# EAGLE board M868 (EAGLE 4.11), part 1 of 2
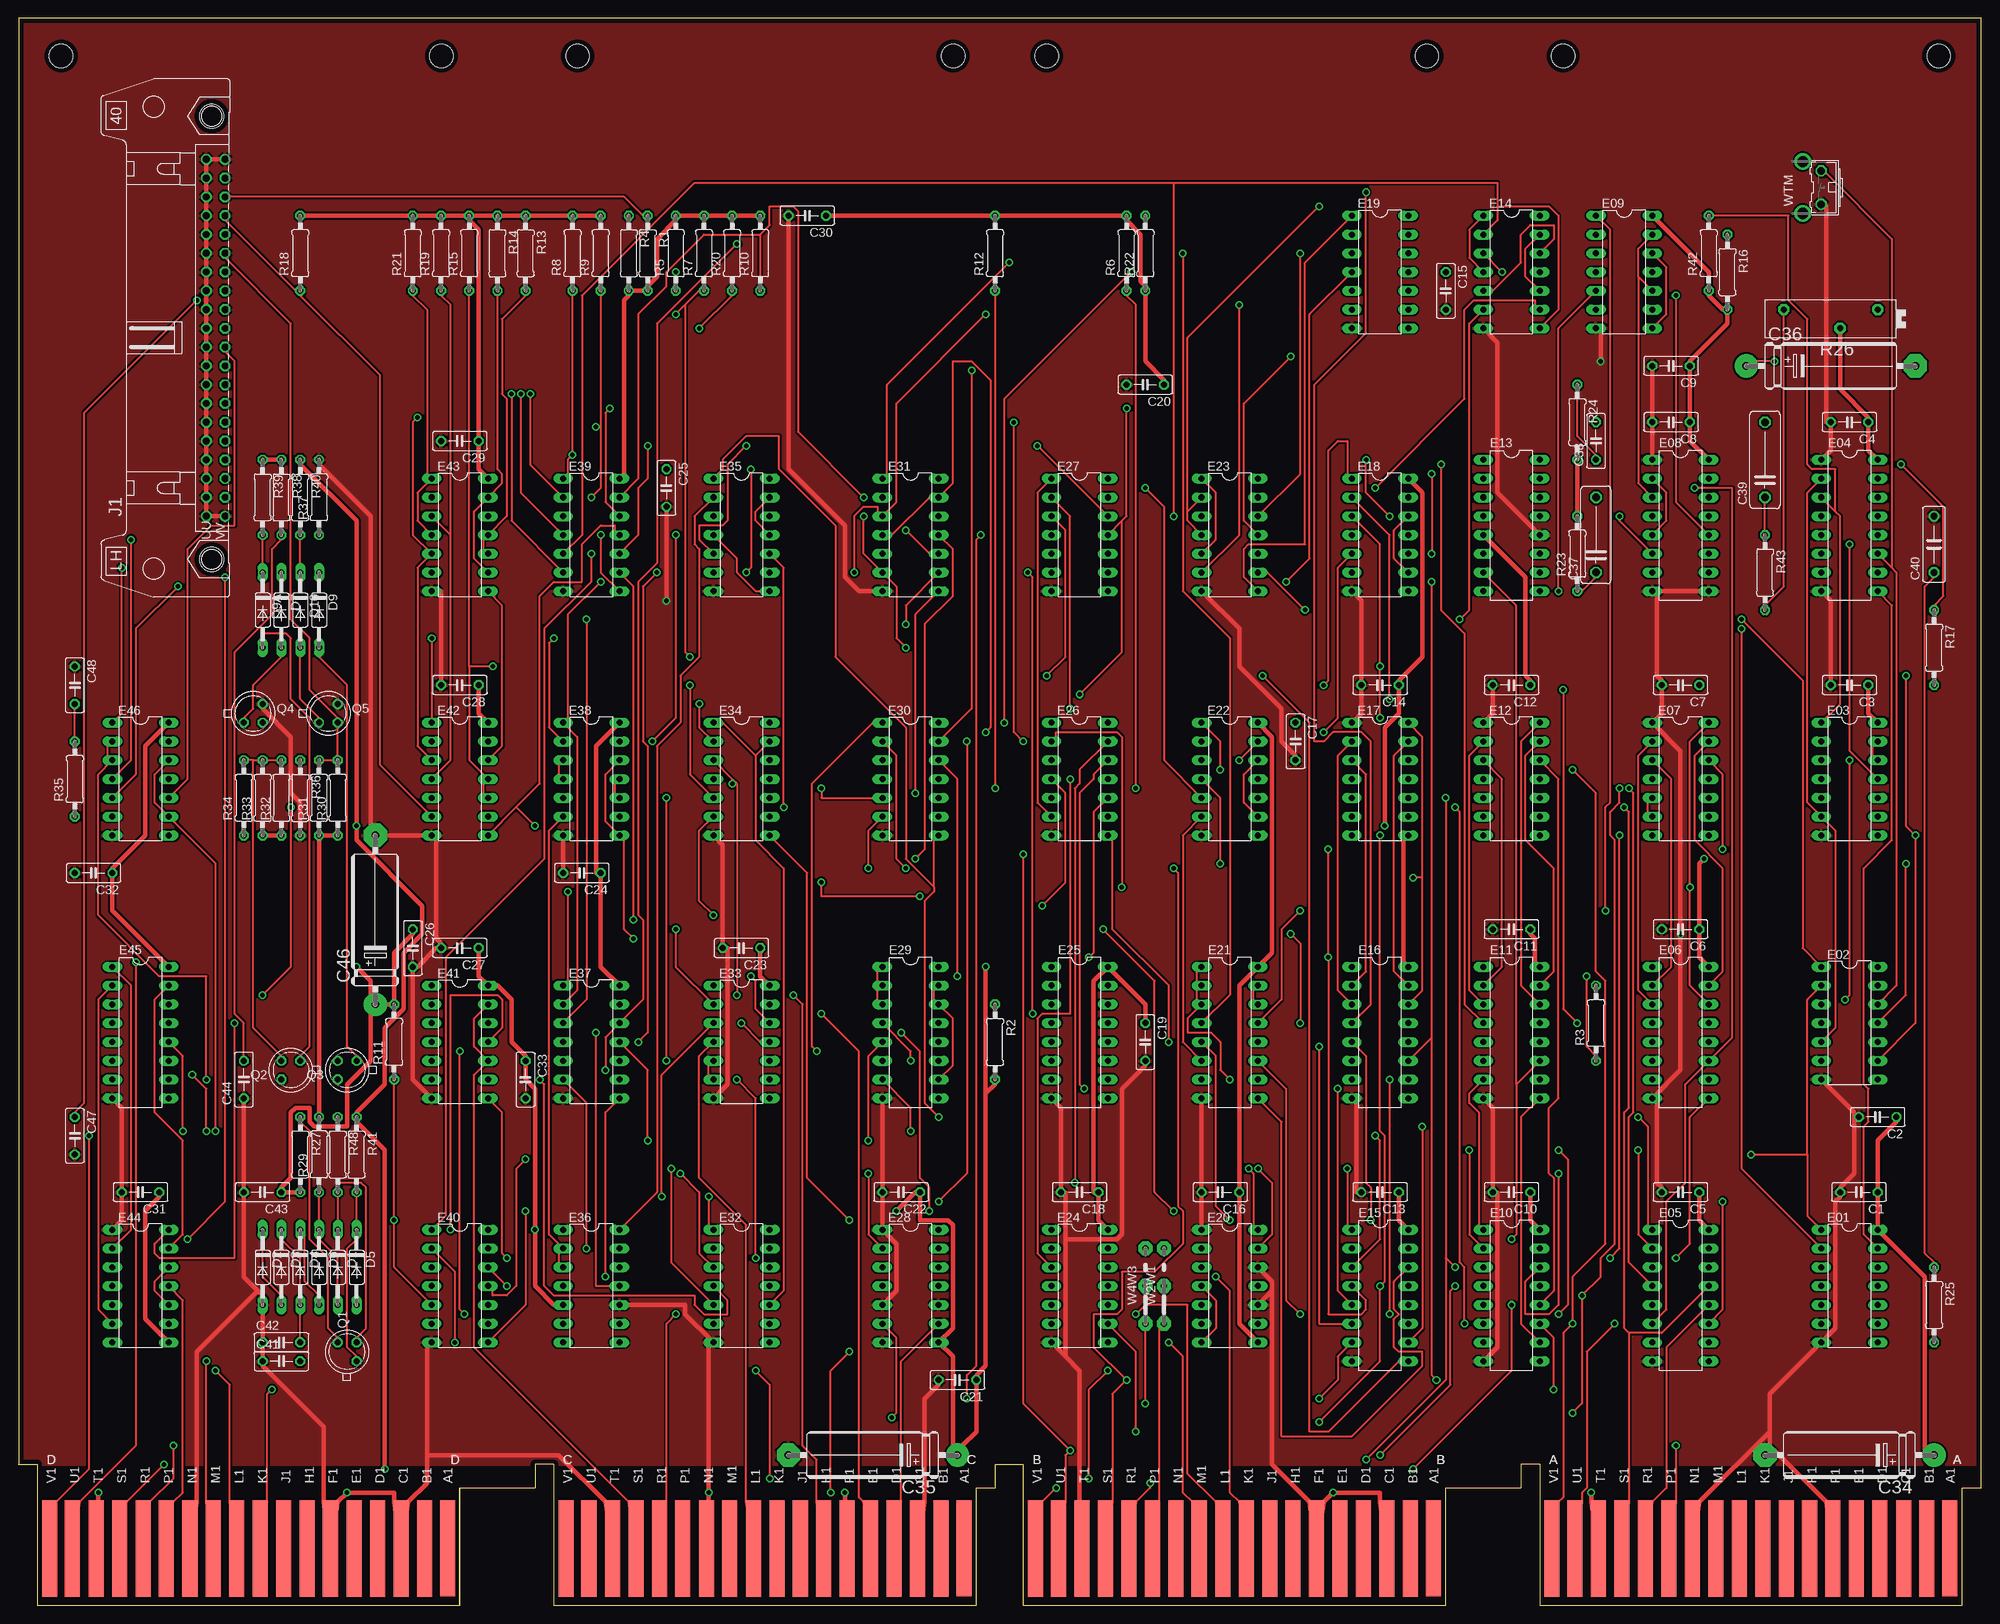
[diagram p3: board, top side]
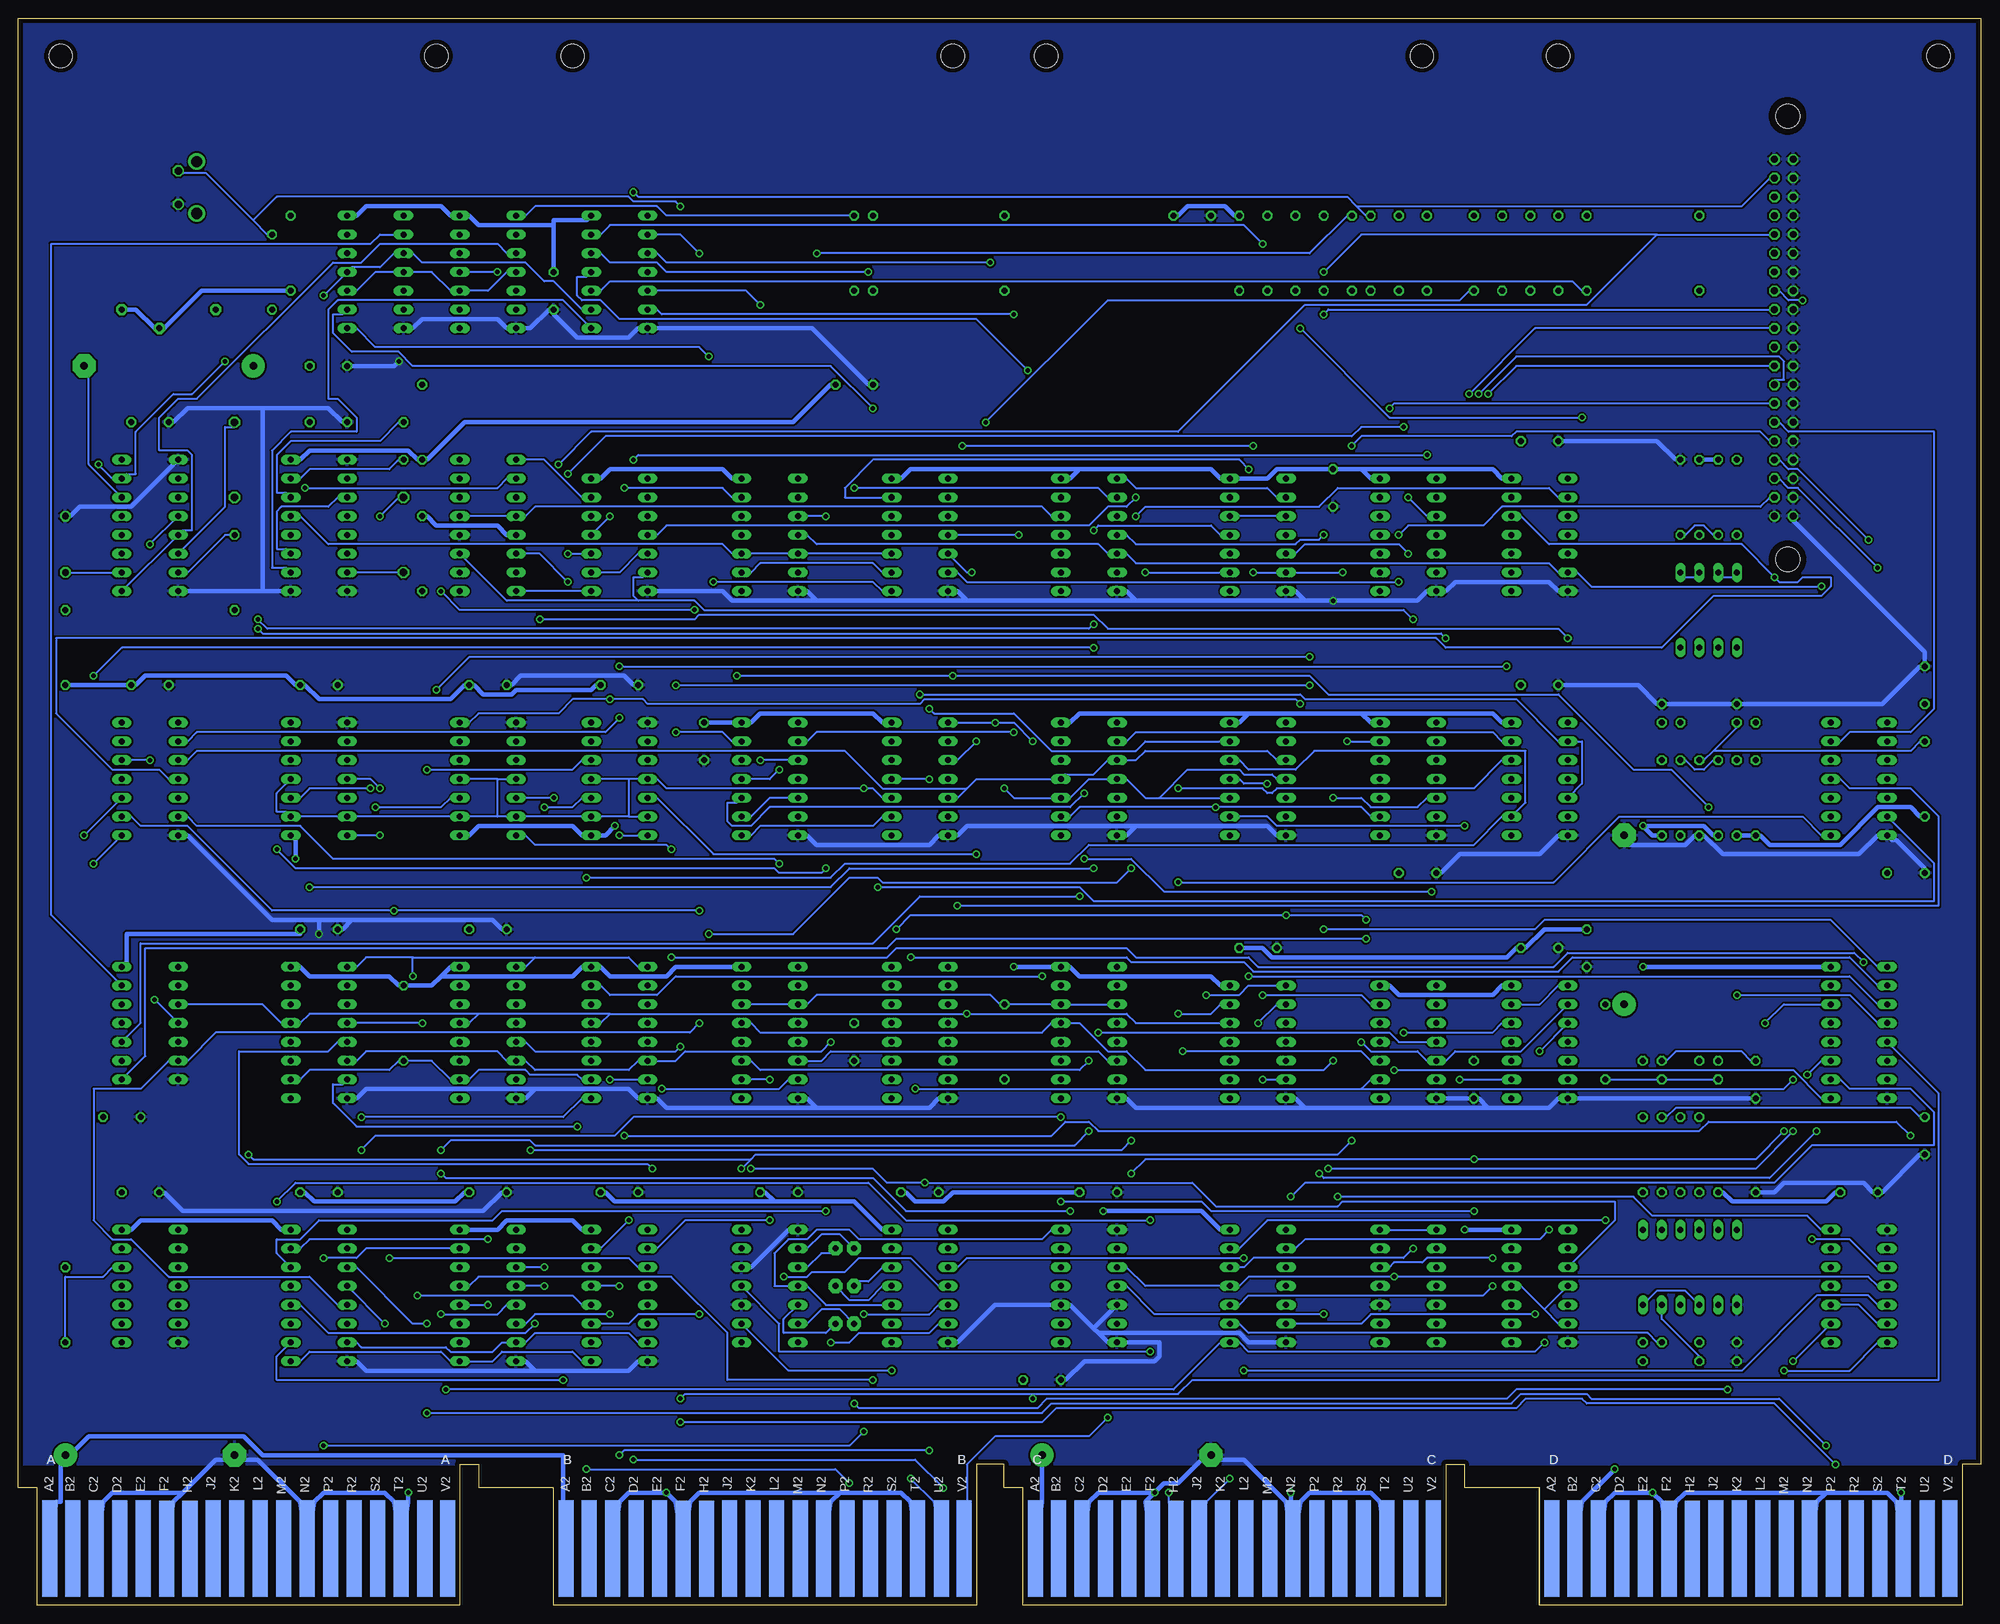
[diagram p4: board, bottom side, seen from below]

Size 265.43 x 214.63 mm. Coordinates in mm from the lower left corner, seen from the top.
Copper layers (1*16): Top 0.035mm / dielectric 1.5mm / Bottom 0.035mm
Design rules "10mils": minimum track width 10mil, minimum drill 24mil, track to track 10mil, track to pad 10mil, pad to pad 10mil, via to via 10mil, smd to smd 10mil, copper to edge 25mil, drill to drill 10mil, minimum pad ring 10mil, minimum via ring 8mil, stop-mask expansion 0mil, vias tented up to drill 0mil, thermal gap 10mil
Net classes: 1 supply: width 0.635 mm

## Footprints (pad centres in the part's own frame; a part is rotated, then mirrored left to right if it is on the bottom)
C050-025X075 = drill 0.813 octagon: 1 -2.54,0; 2 2.54,0
E22-6 = drill 1.016 pad 3.15 round: + -11.43,0 | drill 1.016 pad 3.15 octagon: - 11.43,0
C102-043X133 = drill 1.016 octagon: 1 -5.08,0; 2 5.08,0
C075-032X103 = drill 0.914 octagon: 1 -3.81,0; 2 3.81,0
DO35-10 = drill 0.813 long: A 5.08,0; C -5.08,0
DIL14 = drill 0.813 long: 1 -7.62,-3.81; 2 -5.08,-3.81; 3 -2.54,-3.81; 4 0,-3.81; 5 2.54,-3.81; 6 5.08,-3.81; 7 7.62,-3.81; 8 7.62,3.81; 9 5.08,3.81; 10 2.54,3.81; 11 0,3.81; 12 -2.54,3.81; 13 -5.08,3.81; 14 -7.62,3.81
DIL16 = drill 0.813 long: 1 -8.89,-3.81; 2 -6.35,-3.81; 3 -3.81,-3.81; 4 -1.27,-3.81; 5 1.27,-3.81; 6 3.81,-3.81; 7 6.35,-3.81; 8 8.89,-3.81; 9 8.89,3.81; 10 6.35,3.81; 11 3.81,3.81; 12 1.27,3.81; 13 -1.27,3.81; 14 -3.81,3.81; 15 -6.35,3.81; 16 -8.89,3.81
EDGE-CON8 = smd 2.032 x 13.017: AA1 261.223,7.709; AB1 258.118,7.684; AC1 254.956,7.684; AD1 251.765,7.684; AE1 248.59,7.693; AF1 245.389,7.668; AH1 242.24,7.668; AJ1 239.09,7.668; AK1 235.915,7.668; AL1 232.74,7.693; AM1 229.54,7.693; AN1 226.39,7.693; AP1 223.19,7.668; AR1 220.04,7.668; AS1 216.865,7.693; AT1 213.69,7.693; AU1 210.49,7.693; AV1 207.404,7.668; BA1 191.373,7.709; BB1 188.268,7.684; BC1 185.106,7.684; BD1 181.915,7.684; BE1 178.74,7.693; BF1 175.539,7.668; BH1 172.39,7.668; BJ1 169.24,7.668; BK1 166.065,7.668; BL1 162.89,7.693; BM1 159.69,7.693; BN1 156.54,7.693; BP1 153.34,7.668; BR1 150.19,7.668; BS1 147.015,7.693; BT1 143.84,7.693; BU1 140.64,7.693; BV1 137.554,7.668; CA1 127.873,7.709; CB1 124.768,7.684; CC1 121.606,7.684; CD1 118.415,7.684; CE1 115.24,7.693; CF1 112.039,7.668; CH1 108.89,7.668; CJ1 105.74,7.668; CK1 102.565,7.668; CL1 99.39,7.693; CM1 96.19,7.693; CN1 93.04,7.693; CP1 89.84,7.668; CR1 86.69,7.668; CS1 83.515,7.693; CT1 80.34,7.693; CU1 77.14,7.693; CV1 74.054,7.668; DA1 58.023,7.709; DB1 54.918,7.684; DC1 51.756,7.684; DD1 48.565,7.684; DE1 45.39,7.693; DF1 42.189,7.668; DH1 39.04,7.668; DJ1 35.89,7.668; DK1 32.715,7.668; DL1 29.54,7.693; DM1 26.34,7.693; DN1 23.19,7.693; DP1 19.99,7.668; DR1 16.84,7.668; DS1 13.665,7.693; DT1 10.49,7.693; DU1 7.29,7.693; DV1 4.204,7.668 | smd 2.032 x 13.017 bottom: AA2 261.223,7.69; AB2 258.102,7.668; AC2 254.94,7.668; AD2 251.765,7.693; AE2 248.59,7.693; AF2 245.389,7.642; AH2 242.24,7.642; AJ2 239.09,7.668; AK2 235.915,7.668; AL2 232.74,7.693; AM2 229.54,7.693; AN2 226.39,7.693; AP2 223.19,7.668; AR2 220.04,7.668; AS2 216.865,7.693; AT2 213.69,7.693; AU2 210.464,7.693; AV2 207.404,7.668; BA2 191.373,7.69; BB2 188.252,7.668; BC2 185.09,7.668; BD2 181.915,7.693; BE2 178.74,7.693; BF2 175.539,7.642; BH2 172.39,7.642; BJ2 169.24,7.668; BK2 166.065,7.668; BL2 162.89,7.693; BM2 159.69,7.693; BN2 156.54,7.693; BP2 153.34,7.668; BR2 150.19,7.668; BS2 147.015,7.693; BT2 143.84,7.693; BU2 140.614,7.693; BV2 137.554,7.668; CA2 127.873,7.69; CB2 124.752,7.668; CC2 121.59,7.668; CD2 118.415,7.693; CE2 115.24,7.693; CF2 112.039,7.642; CH2 108.89,7.642; CJ2 105.74,7.668; CK2 102.565,7.668; CL2 99.39,7.693; CM2 96.19,7.693; CN2 93.04,7.693; CP2 89.84,7.668; CR2 86.69,7.668; CS2 83.515,7.693; CT2 80.34,7.693; CU2 77.114,7.693; CV2 74.054,7.668; DA2 58.023,7.69; DB2 54.902,7.668; DC2 51.74,7.668; DD2 48.565,7.693; DE2 45.39,7.693; DF2 42.189,7.642; DH2 39.04,7.642; DJ2 35.89,7.668; DK2 32.715,7.668; DL2 29.54,7.693; DM2 26.34,7.693; DN2 23.19,7.693; DP2 19.99,7.668; DR2 16.84,7.668; DS2 13.665,7.693; DT2 10.49,7.693; DU2 7.264,7.693; DV2 4.204,7.668
DEC40PINH = drill 0.914 octagon: A 24.13,1.27; AA -3.81,1.27; B 24.13,-1.27; BB -3.81,-1.27; C 21.59,1.27; CC -6.35,1.27; D 21.59,-1.27; DD -6.35,-1.27; E 19.05,1.27; EE -8.89,1.27; F 19.05,-1.27; FF -8.89,-1.27; H 16.51,1.27; HH -11.43,1.27; J 16.51,-1.27; JJ -11.43,-1.27; K 13.97,1.27; KK -13.97,1.27; L 13.97,-1.27; LL -13.97,-1.27; M 11.43,1.27; MM -16.51,1.27; N 11.43,-1.27; NN -16.51,-1.27; P 8.89,1.27; PP -19.05,1.27; R 8.89,-1.27; RR -19.05,-1.27; S 6.35,1.27; SS -21.59,1.27; T 6.35,-1.27; TT -21.59,-1.27; U 3.81,1.27; UU -24.13,1.27; V 3.81,-1.27; W 1.27,1.27; X 1.27,-1.27; Y -1.27,1.27; Z -1.27,-1.27 | drill 0.914 round: VV -24.13,-1.27 | hole 3.302: -29.972,0.533; 29.972,0.533
TO18 = drill 0.813 octagon: 1 -1.27,-1.27; 2 1.27,-1.27; 3 1.27,1.27
0207/10 = drill 0.813 octagon: 1 -5.08,0; 2 5.08,0
PT-SPIN = drill 0.813 pad 1.524 octagon: 1 -6.35,-1.27; 2 6.35,-1.27; 3 -1.27,1.27
OMNIBUS = hole 3.175: 208.915,209.55; 259.715,209.55; 190.5,209.55; 139.065,209.55; 75.616,209.55; 126.416,209.55; 57.201,209.55; 5.766,209.55
05C = drill 0.813 pad 1.905 octagon: 1 -2.54,0; 2 2.54,0; 3 7.62,0
B3F-31XX = drill 1.016 octagon: 1 -2.261,-1.245; 2 2.261,-1.245 | drill 1.499 pad 2.159 round: 3 -3.505,1.245; 4 3.505,1.245

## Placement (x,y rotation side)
C1  .01  [C050-025X075]  248.92,55.88 180 top
C2  .01  [C050-025X075]  251.46,66.04 180 top
C3  .01  [C050-025X075]  247.65,124.46 180 top
C4  .01  [C050-025X075]  247.65,160.02 180 top
C5  .01  [C050-025X075]  224.79,55.88 180 top
C6  .01  [C050-025X075]  224.79,91.44 180 top
C7  .01  [C050-025X075]  224.79,124.46 180 top
C8  .01  [C050-025X075]  223.52,160.02 180 top
C9  .01  [C050-025X075]  223.52,167.64 180 top
C10  .01  [C050-025X075]  201.93,55.88 180 top
C11  .01  [C050-025X075]  201.93,91.44 180 top
C12  .01  [C050-025X075]  201.93,124.46 180 top
C13  .01  [C050-025X075]  184.15,55.88 180 top
C14  .01  [C050-025X075]  184.15,124.46 180 top
C15  .01  [C050-025X075]  193.04,177.8 270 top
C16  .01  [C050-025X075]  162.56,55.88 180 top
C17  .01  [C050-025X075]  172.72,116.84 270 top
C18  .01  [C050-025X075]  143.51,55.88 180 top
C19  .01  [C050-025X075]  152.4,76.2 270 top
C20  .01  [C050-025X075]  152.4,165.1 180 top
C21  .01  [C050-025X075]  127,30.48 180 top
C22  .01  [C050-025X075]  119.38,55.88 180 top
C23  .01  [C050-025X075]  97.79,88.9 180 top
C24  .01  [C050-025X075]  76.2,99.06 180 top
C25  .01  [C050-025X075]  87.63,151.13 270 top
C26  .01  [C050-025X075]  53.34,88.9 270 top
C27  .01  [C050-025X075]  59.69,88.9 180 top
C28  .01  [C050-025X075]  59.69,124.46 180 top
C29  .01  [C050-025X075]  59.69,157.48 180 top
C30  .01  [C050-025X075]  106.68,187.96 180 top
C31  .01  [C050-025X075]  16.51,55.88 180 top
C32  .01  [C050-025X075]  10.16,99.06 180 top
C33  .01  [C050-025X075]  68.58,71.12 270 top
C34  6.8  [E22-6]  247.65,20.32 180 top
C35  6.8  [E22-6]  115.57,20.32 180 top
C36  6.8  [E22-6]  245.11,167.64 0 top
C37  2700pf  [C102-043X133]  213.36,144.78 90 top
C38  27pf  [C050-025X075]  213.36,157.48 90 top
C39  2700pf  [C102-043X133]  236.22,154.94 90 top
C40  560pf  [C075-032X103]  259.08,143.51 90 top
C41  .01  [C050-025X075]  35.56,33.02 0 top
C42  .01  [C050-025X075]  35.56,35.56 0 top
C43  .01  [C050-025X075]  33.02,55.88 180 top
C44  .01  [C050-025X075]  30.48,71.12 90 top
C46  6.8  [E22-6]  48.26,92.71 90 top
C47  .01  [C050-025X075]  7.62,63.5 270 top
C48  .01  [C050-025X075]  7.62,124.46 270 top
D1  D664  [DO35-10]  43.18,45.72 270 top
D2  D662  [DO35-10]  33.02,45.72 270 top
D3  D662  [DO35-10]  35.56,45.72 270 top
D4  D662  [DO35-10]  38.1,45.72 270 top
D5  D664  [DO35-10]  45.72,45.72 270 top
D6  D662  [DO35-10]  40.64,45.72 270 top
D7  D664  [DO35-10]  35.56,134.62 270 top
D9  D664  [DO35-10]  40.64,134.62 270 top
D9A  D664  [DO35-10]  33.02,134.62 270 top
D10  D664  [DO35-10]  38.1,134.62 270 top
E01  74H04N  [DIL14]  247.65,43.18 270 top
E02  7402N  [DIL14]  247.65,78.74 270 top
E03  7474N  [DIL14]  247.65,111.76 270 top
E04  74123N  [DIL16]  247.65,146.05 270 top
E05  DEC8235  [DIL16]  224.79,41.91 270 top
E06  DEC8271  [DIL16]  224.79,77.47 270 top
E07  SP380N  [DIL14]  224.79,111.76 270 top
E08  74123N  [DIL16]  224.79,146.05 270 top
E09  7474N  [DIL14]  217.17,180.34 270 top
E10  DEC8235  [DIL16]  201.93,41.91 270 top
E11  DEC8271  [DIL16]  201.93,77.47 270 top
E12  SP380N  [DIL14]  201.93,111.76 270 top
E13  7475N  [DIL16]  201.93,146.05 270 top
E14  7474N  [DIL14]  201.93,180.34 270 top
E15  DEC8235  [DIL16]  184.15,41.91 270 top
E16  DEC8271  [DIL16]  184.15,77.47 270 top
E17  SP380N  [DIL14]  184.15,111.76 270 top
E18  DEC8242  [DIL14]  184.15,144.78 270 top
E19  7400N  [DIL14]  184.15,180.34 270 top
E20  SP380N  [DIL14]  163.83,43.18 270 top
E21  DEC8271  [DIL16]  163.83,77.47 270 top
E22  7400N  [DIL14]  163.83,111.76 270 top
E23  7410N  [DIL14]  163.83,144.78 270 top
E24  SP314N  [DIL14]  143.51,43.18 270 top
E25  [DIL16]  143.51,77.47 270 top
E26  7404N  [DIL14]  143.51,111.76 270 top
E27  7410N  [DIL14]  143.51,144.78 270 top
E28  SP384N  [DIL14]  120.65,43.18 270 top
E29  DEC8271  [DIL16]  120.65,77.47 270 top
E30  7474N  [DIL14]  120.65,111.76 270 top
E31  7404N  [DIL14]  120.65,144.78 270 top
E32  7404N  [DIL14]  97.79,43.18 270 top
E33  DS8881N  [DIL14]  97.79,76.2 270 top
E34  7474N  [DIL14]  97.79,111.76 270 top
E35  7410N  [DIL14]  97.79,144.78 270 top
E36  74LS93N  [DIL14]  77.47,43.18 270 top
E37  7402N  [DIL14]  77.47,76.2 270 top
E38  7400N  [DIL14]  77.47,111.76 270 top
E39  7417N  [DIL14]  77.47,144.78 270 top
E40  7430N  [DIL14]  59.69,43.18 270 top
E41  DS8881N  [DIL14]  59.69,76.2 270 top
E42  DEC8242  [DIL14]  59.69,111.76 270 top
E43  7401N  [DIL14]  59.69,144.78 270 top
E44  SP380N  [DIL14]  16.51,43.18 270 top
E45  DEC8251  [DIL16]  16.51,77.47 270 top
E46  7401N  [DIL14]  16.51,111.76 270 top
EDGE$  [EDGE-CON8]  0,0 0 top
J1  [DEC40PINH]  26.67,171.45 90 top
Q1  MPS6534  [TO18]  44.45,34.29 90 top
Q2  MPS6534  [TO18]  36.83,72.39 180 top
Q3  MPS6534  [TO18]  44.45,72.39 180 top
Q4  MPS6534  [TO18]  31.75,120.65 0 top
Q5  MPS6534  [TO18]  41.91,120.65 0 top
R1  270  [0207/10]  85.09,182.88 270 top
R2  1K  [0207/10]  132.08,76.2 270 top
R3  1K  [0207/10]  213.36,78.74 90 top
R4  270  [0207/10]  82.55,182.88 270 top
R5  270  [0207/10]  88.9,182.88 90 top
R6  560  [0207/10]  149.86,182.88 90 top
R7  270  [0207/10]  92.71,182.88 90 top
R8  470  [0207/10]  74.93,182.88 90 top
R9  470  [0207/10]  78.74,182.88 90 top
R10  470  [0207/10]  100.33,182.88 90 top
R11  6.8K  [0207/10]  50.8,76.2 90 top
R12  1K  [0207/10]  132.08,182.88 90 top
R13  470  [0207/10]  68.58,182.88 270 top
R14  470  [0207/10]  64.77,182.88 270 top
R15  470  [0207/10]  60.96,182.88 90 top
R16  1.5K  [0207/10]  231.14,180.34 270 top
R17  51K  [0207/10]  259.08,129.54 270 top
R18  270  [0207/10]  38.1,182.88 90 top
R19  470  [0207/10]  57.15,182.88 90 top
R20  470  [0207/10]  96.52,182.88 90 top
R21  470  [0207/10]  53.34,182.88 90 top
R22  1K  [0207/10]  152.4,182.88 90 top
R23  10K  [0207/10]  210.82,142.24 90 top
R24  4.7K  [0207/10]  210.82,160.02 270 top
R25  220  [0207/10]  259.08,40.64 270 top
R26  10K  [PT-SPIN]  245.11,173.99 180 top
R27  1.5K  [0207/10]  38.1,60.96 270 top
R29  1.5K  [0207/10]  40.64,60.96 90 top
R30  1K  [0207/10]  43.18,109.22 90 top
R31  1K  [0207/10]  40.64,109.22 90 top
R32  1K  [0207/10]  35.56,109.22 90 top
R33  1K  [0207/10]  33.02,109.22 90 top
R34  1K  [0207/10]  30.48,109.22 90 top
R35  1.21K 1%  [0207/10]  7.62,111.76 90 top
R36  562 1%  [0207/10]  38.1,109.22 270 top
R37  1.5K  [0207/10]  40.64,149.86 90 top
R38  1K  [0207/10]  35.56,149.86 270 top
R39  1.5K  [0207/10]  33.02,149.86 270 top
R40  1K  [0207/10]  38.1,149.86 270 top
R41  3K  [0207/10]  45.72,60.96 270 top
R42  1K  [0207/10]  228.6,182.88 90 top
R43  4.7K  [0207/10]  236.22,139.7 270 top
R48  470  [0207/10]  43.18,60.96 270 top
U$1  OUTLINE-OMNIBUS  [OMNIBUS]  0,0 0 top
W2W1  [05C]  154.94,40.64 90 top
W4W3  [05C]  152.4,40.64 90 top
WTM  [B3F-31XX]  242.57,191.77 90 top

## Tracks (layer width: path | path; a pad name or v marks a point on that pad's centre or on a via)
-1.5V
  Top 0.254: C42.2 D4.A 38.1,46.99 35.56,49.53 D3.C
  Bottom 0.254: D5.A 43.81,42.55 40.01,42.55 D4.A
-3V
  Top 0.254: R29.1 D6.C 40.64,49.53 43.18,46.99 D1.A
  Bottom 0.254: C41.2 38.1,33.66 43.18,38.74 D1.A
-4.7V
  Top 0.254: R35.2 C48.2
  Bottom 0.254: 36.2,115.57 33.02,118.75 Q4.2 | 36.2,115.57 37.47,114.3 R36.1 | 36.2,115.57 9.53,115.57 8.26,116.84 R35.2
-9V
  Top 0.254: R38.2 35.56,144.15 34.29,142.88 34.29,133.99 29.21,128.91 29.21,80.01 30.48,78.74 C44.2
  Bottom 0.254: R38.2 36.2,144.78 37.47,146.05 38.73,146.05 40.01,144.78 R37.1 | C44.2 31.11,73.66 32.38,74.93 41.27,74.93 42.55,73.66 Q3.2
-15V  (via drill 0.61)
  Top 0.635: v49.53,18.42 49.53,61.6 45.72,65.41 R41.1 45.72,66.68 49.53,70.49 49.53,78.11 52.07,80.65 52.07,88.27 54.61,90.81 54.61,94.62 45.72,103.51 v45.72,105.41 45.72,146.69 38.1,154.31 R40.1 | R32.1 R33.1 | R38.1 R39.1 | R29.2 R31.1 R30.1
  Bottom 0.635: v49.53,18.42 53.98,13.97 EDGE$.DB2 | R33.1 R34.1 29.84,104.14 28.57,102.87 19.05,102.87 13.97,107.95 9.53,107.95 8.26,106.68 R35.1 | R40.1 R38.1 | R30.1 44.45,104.14 v45.72,105.41 37.47,105.41 36.2,104.14 R32.1
C0  (via drill 0.61)
  Top 0.254: v108.58,80.01 113.67,74.93 113.67,14.61 114.3,13.97 EDGE$.CE1
  Bottom 0.254: v108.58,80.01 104.14,80.01 102.87,81.28 E33.13
C1  (via drill 0.61)
  Top 0.254: v104.78,82.55 106.05,81.28 106.05,21.59 107.95,19.69 107.95,13.97 EDGE$.CH1
  Bottom 0.254: v104.78,82.55 100.33,82.55 99.06,83.82 E33.1
CC_67X  (via drill 0.61)
  Top 0.254: E33.6 93.34,71.76 93.34,73.03 E33.5 | v142.24,111.76 142.24,80.01 138.43,80.01 137.79,79.38 137.79,47.63 E24.3 | v97.16,71.12 99.69,68.58 v99.69,46.99
  Bottom 0.254: v142.24,111.76 E26.11 | v99.69,46.99 137.16,46.99 138.43,45.72 E24.3 | v97.16,71.12 E33.6
CC_67X\  (via drill 0.61)
  Top 0.254: E45.2 10.79,81.92 10.79,40.01 E44.6 | E44.12 18.41,43.82 18.41,42.55 E44.10 | E07.6 220.34,107.32 220.34,108.59 E07.5 | v151.13,110.49 151.13,175.9 149.86,177.17 R6.1 | v144.78,87.63 145.41,88.27 145.41,107.32 E26.10
  Bottom 0.254: E44.6 13.97,38.1 16.51,40.64 E44.10 | E07.11 230.5,109.86 230.5,107.32 229.24,107.32 E07.9 E07.6 E12.9 200.66,106.68 | 200.66,106.68 E12.6 E17.9 182.88,106.68 | 200.66,111.76 E12.4 | 200.66,111.76 E12.11 | 200.66,106.68 200.66,111.76 | 182.88,106.68 E17.6 | E26.10 148.59,109.22 149.86,110.49 v151.13,110.49 177.8,110.49 179.07,111.76 E17.4 182.88,111.76 | 182.88,111.76 E17.11 | 182.88,111.76 182.88,106.68 | v144.78,87.63 115.57,87.63 114.94,87 99.69,87 98.42,85.73 57.15,85.73 55.24,87.63 17.78,87.63 13.97,83.82 E45.2
CC_BTP3  (via drill 0.61)
  Top 0.254: v233.04,132.08 233.04,59.06 E01.2 | v72.39,130.81 71.75,130.18 71.75,118.75 E38.2
  Bottom 0.254: v233.04,132.08 232.41,131.45 73.03,131.45 v72.39,130.81
CC_CLK_TE\
  Top 0.254: E26.6 137.79,108.59 137.79,150.5 E27.1
CC_DTP
  Top 0.254: E23.1 161.93,150.5 161.93,144.15 E23.5
  Bottom 0.254: E27.10 E23.5 E23.10 168.91,142.24 170.18,143.51 223.52,143.51 227.33,147.32 E08.13
CC_DTP0  (via drill 0.61)
  Top 0.254: v113.03,139.7 113.03,147.32 114.3,148.59 116.2,148.59 116.2,147.96 E31.3 118.75,149.23 118.75,162.56 v130.81,174.63
  Bottom 0.254: v113.03,139.7 E35.9 | v130.81,174.63 178.44,174.63 179.07,175.26 E19.6
CC_DTP0\  (via drill 0.61)
  Top 0.254: v85.72,116.84 88.9,120.02 v88.9,144.78 | E31.4 118.11,144.78 123.19,149.86 E31.13 126.36,151.77 126.36,168.28 128.91,168.28 131.44,165.74 131.44,118.75 v130.81,118.11
  Bottom 0.254: v88.9,144.78 89.53,144.15 92.08,144.15 92.71,143.51 114.3,143.51 115.57,144.78 E31.4 | v85.72,116.84 E38.13 | v130.81,118.11 157.48,118.11 158.75,116.84 E22.2
CC_DTP1  (via drill 0.61)
  Top 0.254: v133.99,181.61 117.47,165.1 117.47,153.04 E31.1 | E36.14 86.36,55.88 86.36,116.21 89.53,119.38 89.53,125.73 92.08,128.27 92.08,142.88 91.44,143.51 91.44,147.32 E35.2
  Bottom 0.254: E36.14 E36.1 | E35.2 95.25,149.86 96.52,151.13 114.3,151.13 115.57,152.4 E31.1 | v133.99,181.61 177.8,181.61 179.07,182.88 E19.3
CC_DTP1\  (via drill 0.61)
  Top 0.254: v152.4,151.13 154.94,148.59 154.94,114.3 E22.5 | E22.12 165.74,112.4 165.74,108.59 E22.9
  Bottom 0.254: v152.4,151.13 119.38,151.13 118.11,149.86 E31.2 | E22.9 166.37,106.68 163.83,109.22 E22.5
CC_F/R  (via drill 0.61)
  Top 0.254: v90.81,124.46 90.81,112.4 E34.5 | v176.53,124.46 177.16,125.1 177.16,156.21 178.44,157.48 179.71,157.48 179.71,153.04 E18.1
  Bottom 0.254: v176.53,124.46 v90.81,124.46
CC_F/R\  (via drill 0.61)
  Top 0.254: v156.21,53.34 153.67,55.88 153.67,84.46 v146.69,91.44 | v93.98,93.35 92.08,95.25 92.08,104.78 E34.6 | v83.19,92.71 83.19,137.8 E39.9
  Bottom 0.254: v156.21,53.34 200.03,53.34 201.29,52.07 224.79,52.07 227.33,49.53 230.5,49.53 230.5,47.63 E05.14 | v146.69,91.44 144.78,93.35 v93.98,93.35 83.82,93.35 v83.19,92.71
CC_INIT  (via drill 0.61)
  Top 0.254: v79.38,44.45 79.38,66.68 E37.8
  Bottom 0.254: E44.4 13.97,43.18 15.24,44.45 v79.38,44.45 99.06,44.45 100.33,43.18 E32.11 113.03,43.18 115.57,45.72 E28.3
CC_INIT\  (via drill 0.61)
  Top 0.254: 99.69,114.94 99.69,103.51 103.5,99.7 103.5,42.55 E32.10 | E34.13 99.69,114.94 | v66.04,43.18 E40.12 | 99.69,114.94 95.25,119.38 E34.1 | v142.24,121.29 142.24,147.32 E27.2
  Bottom 0.254: v66.04,43.18 67.31,41.91 99.06,41.91 100.33,40.64 E32.10 | v142.24,121.29 141.6,120.65 130.81,120.65 125.73,115.57 114.3,115.57 113.03,116.84 E34.13
CC_PWR_OK  (via drill 0.61)
  Top 0.254: E46.12 18.41,112.4 18.41,108.59 E46.9 26.67,100.33 v26.67,64.14 | v114.94,58.42 114.94,50.17 E28.2 | v68.58,60.33 67.31,59.06 67.31,43.18 66.04,41.91 64.14,41.91 64.14,42.55 E40.11
  Bottom 0.254: 59.05,40.01 62.23,43.18 E40.11 | 59.05,40.01 57.15,38.1 E40.6 | 59.05,40.01 E40.4 | v114.94,58.42 113.03,60.33 v68.58,60.33 30.48,60.33 v26.67,64.14
CC_R/W  (via drill 0.61)
  Top 0.254: v103.5,107.95 103.5,140.34 E35.10
  Bottom 0.254: E38.9 82.55,106.68 83.82,107.95 v103.5,107.95 121.92,107.95 123.19,106.68 E30.9
CC_R/W\  (via drill 0.61)
  Top 0.254: v219.07,61.6 219.07,50.17 E05.2 | v124.46,66.04 122.56,67.95 122.56,95.25 123.83,96.52 123.83,97.16 | 123.83,97.16 123.83,103.51 E30.8 | 123.83,97.16 120.02,100.97 120.02,118.75 110.49,128.27 110.49,146.05 102.87,153.67 102.87,158.12 98.42,158.12 95.25,154.94 95.25,153.67 E35.1
  Bottom 0.254: v219.07,61.6 217.17,63.5 184.78,63.5 182.25,66.04 v124.46,66.04
CC_RUN  (via drill 0.61)
  Top 0.254: E46.2 12.06,116.21 12.06,114.94 E46.3 10.79,112.4 10.79,93.35 19.05,85.09 25.4,85.09 v25.4,71.12 | v144.15,69.85 143.51,70.49 143.51,109.86 145.41,111.76 145.41,112.4 E26.12
  Bottom 0.254: 83.82,69.85 82.55,71.12 E37.9 | v144.15,69.85 83.82,69.85 | v25.4,71.12 26.67,69.85 83.82,69.85
CC_RUN\  (via drill 0.61)
  Top 0.254: v166.37,59.06 167,58.42 167,51.44 E20.14 | v142.88,57.15 142.88,110.49 143.51,111.13 143.51,113.03 E26.13
  Bottom 0.254: v166.37,59.06 149.86,59.06 147.96,57.15 v142.88,57.15 106.68,57.15 103.5,53.98 87,53.98 86.36,54.61 49.53,54.61 49.53,52.07 E40.3
CC_S/G  (via drill 0.61)
  Top 0.254: E42.12 65.41,116.21 65.41,135.26 E43.8 | v108.58,110.49 108.58,109.22 E30.5
  Bottom 0.254: v108.58,110.49 97.16,110.49 96.52,109.86 95.89,109.86 95.25,110.49 68.58,110.49 64.77,114.3 E42.12
CC_S/G\  (via drill 0.61)
  Top 0.254: v114.94,99.7 114.94,104.78 E30.6 | v172.09,90.81 173.35,89.54 v173.35,78.74
  Bottom 0.254: E05.5 222.25,40.64 226.06,44.45 245.11,44.45 250.19,49.53 252.73,49.53 255.27,52.07 255.27,69.85 248.92,69.85 245.11,73.66 E02.6 242.57,73.66 238.76,77.47 174.62,77.47 v173.35,78.74 | v114.94,99.7 116.84,97.79 148.59,97.79 149.22,98.43 153.03,98.43 160.66,90.81 v172.09,90.81
CC_SDLC\  (via drill 0.61)
  Top 0.254: v79.38,72.39 79.38,76.84 E37.12 84.45,81.92 84.45,92.71 83.82,93.35 83.82,138.43 86.36,140.97 86.36,173.36 v97.16,184.15
  Bottom 0.254: v79.38,72.39 25.4,72.39 21.59,68.58 E45.9 | v97.16,184.15 99.69,186.69 185.42,186.69 186.69,185.42 E19.13
CC_SDLD\  (via drill 0.61)
  Top 0.254: v99.06,85.09 99.69,84.46 99.69,80.65 E33.12 | v136.53,139.7 137.16,139.07 v137.16,80.01
  Bottom 0.254: E02.3 232.41,81.28 229.87,78.74 E06.13 227.33,78.74 226.06,80.01 203.2,80.01 | 185.42,80.01 v137.16,80.01 115.57,80.01 114.3,78.74 E33.12 | 185.42,80.01 186.69,78.74 E16.13 | 203.2,80.01 204.47,78.74 E11.13 | 185.42,80.01 203.2,80.01 | v99.06,85.09 17.78,85.09 13.97,81.28 E45.3 | v136.53,139.7 137.16,139.7 E27.5
CC_SDRC\  (via drill 0.61)
  Top 0.254: v33.02,82.55 36.83,86.36 v36.83,107.95 | v139.06,125.73 141.6,128.27 141.6,145.42 E27.3 | v168.28,125.73 174.62,119.38 174.62,23.5 177.16,23.5 186.69,33.02 E15.9
  Bottom 0.254: E15.9 189.23,33.02 190.5,34.29 200.03,34.29 201.29,33.02 E10.9 207.01,33.02 208.28,34.29 226.06,34.29 227.33,33.02 E05.9 | v33.02,82.55 17.78,82.55 13.97,78.74 E45.4 | v36.83,107.95 41.91,113.03 46.99,113.03 57.15,123.19 88.27,123.19 90.81,125.73 v139.06,125.73 v168.28,125.73
CC_SDRD\  (via drill 0.61)
  Top 0.254: v175.9,27.94 178.44,30.48 178.44,33.66 E15.7 | v130.18,144.78 129.54,144.15 129.54,32.39 128.27,31.12 v128.27,27.94
  Bottom 0.254: E15.7 181.61,35.56 182.88,36.83 195.58,36.83 196.85,35.56 E10.7 200.03,35.56 201.29,34.29 207.01,34.29 207.65,34.93 219.07,34.93 219.71,35.56 E05.7 | 128.27,28.58 175.26,28.58 v175.9,27.94 | 128.27,28.58 108.58,28.58 106.68,30.48 5.71,30.48 5.71,69.22 E45.5 | 128.27,28.58 v128.27,27.94 | v130.18,144.78 E27.4
CC_SDSQ\  (via drill 0.61)
  Top 0.254: v93.34,55.25 93.34,51.44 E32.1
  Bottom 0.254: v93.34,55.25 91.44,57.15 27.94,57.15 22.86,62.23 6.35,62.23 6.35,66.68 9.53,69.85 17.78,69.85 19.05,71.12 E45.10
CC_SDSS\  (via drill 0.61)
  Top 0.254: v22.23,64.14 22.23,74.3 E45.12 | v89.53,58.42 92.08,55.88 92.08,47.63 E32.3
  Bottom 0.254: v22.23,64.14 28.57,57.79 88.9,57.79 v89.53,58.42
CC_SDST\  (via drill 0.61)
  Top 0.254: v23.5,71.76 25.4,69.85 v25.4,64.14 | v88.27,59.06 88.27,46.36 E32.5
  Bottom 0.254: v23.5,71.76 21.59,73.66 E45.11 | v25.4,64.14 30.48,59.06 v88.27,59.06
CC_SETDLY\  (via drill 0.61)
  Top 0.254: E02.5 245.75,78.11 245.75,104.78 E03.6 241.94,108.59 241.94,150.5 E04.2 | v162.56,100.33 162.56,109.22 E22.4
  Bottom 0.254: v162.56,100.33 163.19,100.97 222.88,100.97 227.33,105.41 241.3,105.41 242.57,106.68 E03.6
CC_T/M_EN  (via drill 0.61)
  Top 0.254: 253.37,140.34 254,139.7 254,83.82 E02.12 | 253.37,140.34 E04.11 | 253.37,140.34 253.37,184.79 244.47,193.68 WTM.2 | 158.12,147.96 158.12,146.69 E23.4 | 158.12,147.96 E23.2 | v21.59,137.8 15.88,132.08 15.88,112.4 E46.5 | v175.9,189.23 158.12,171.45 158.12,147.96
  Bottom 0.254: 233.68,187.33 240.03,193.68 243.21,193.68 WTM.2 | 233.68,187.33 231.78,185.42 R16.1 | E23.4 158.75,144.78 157.48,143.51 119.38,143.51 118.11,142.24 E31.5 115.57,142.24 114.3,140.97 58.42,140.97 57.15,139.7 E43.6 54.61,139.7 52.7,137.8 v21.59,137.8 | 233.68,187.33 230.5,190.5 182.88,190.5 182.25,189.87 176.53,189.87 v175.9,189.23
CC_T/M_EN\  (via drill 0.61)
  Top 0.254: E02.9 256.54,78.74 v256.54,104.14 255.27,105.41 v255.27,125.73 | v114.3,147.32 114.3,142.24 E31.6 118.75,137.8 118.75,130.81 v120.02,129.54
  Bottom 0.254: v256.54,104.14 E03.10 | v114.3,147.32 113.03,148.59 89.53,148.59 87,151.13 58.42,151.13 57.15,149.86 E43.2 | v255.27,125.73 251.46,129.54 v120.02,129.54
CC_TP3\  (via drill 0.61)
  Top 0.254: 241.94,60.96 241.94,81.92 E02.2 | 241.94,60.96 241.94,52.71 E01.1 | v85.09,62.87 85.09,72.39 E37.11 | v167.64,59.06 169.54,57.15 169.54,50.17 E20.13 | v234.31,60.96 241.94,60.96
  Bottom 0.254: v85.09,62.87 87,60.96 165.74,60.96 166.37,60.33 | 166.37,60.33 v167.64,59.06 | v234.31,60.96 233.68,60.33 166.37,60.33
CC_TPG1
  Top 0.254: E14.5 199.39,177.8 203.2,181.61 203.2,185.42 204.47,186.69 207.65,186.69 207.65,184.79 E14.12
CC_TPG1\  (via drill 0.61)
  Top 0.254: v194.94,133.35 196.22,134.62 196.22,173.36 E14.6 | v55.88,130.81 E42.1
  Bottom 0.254: v55.88,130.81 57.15,132.08 118.11,132.08 120.02,133.99 173.35,133.99 173.99,133.35 v194.94,133.35
CC_TPG_CLK  (via drill 0.61)
  Top 0.254: E14.3 v200.66,180.34 | E01.13 249.56,50.17 249.56,64.77 250.19,65.41 250.19,69.85 249.56,70.49 249.56,99.7 253.37,103.51 253.37,135.26 E04.9
  Bottom 0.254: v200.66,180.34 E14.11 | E04.9 E04.5 243.21,145.42 241.94,145.42 241.94,155.58 242.57,156.21 246.38,156.21 246.38,160.66 243.84,163.2 241.3,163.2 222.88,181.61 219.07,181.61 216.53,184.15 200.66,184.15 199.39,182.88 E14.3
CC_TPG_CLK\
  Top 0.254: R25.1 259.08,46.36 257.81,47.63 257.81,137.8 259.08,139.07 C40.1
  Bottom 0.254: C40.1 E04.10
CC_TT_EN
  Bottom 0.254: E19.8 191.77,176.53 222.25,176.53 223.52,175.26 223.52,163.2 222.25,163.2 219.71,160.66 219.71,158.75 228.6,158.75 231.14,156.21 231.14,140.34 229.24,140.34 E08.10
CC_UNIT  (via drill 0.61)
  Top 0.254: 67.31,107.95 70.48,111.13 70.48,136.53 72.39,138.43 76.2,138.43 76.2,143.51 78.74,146.05 80.64,146.05 80.64,145.42 E39.11 | E42.8 67.31,107.95 | 67.31,107.95 v69.85,105.41
  Bottom 0.254: v69.85,105.41 95.25,105.41 96.52,106.68 E34.9
CC_UNIT\  (via drill 0.61)
  Top 0.254: v230.5,54.61 230.5,40.01 E05.11 | v112.39,52.07 106.68,57.79 106.68,99.06 E34.8
  Bottom 0.254: v230.5,54.61 227.97,57.15 150.5,57.15 145.41,52.07 v112.39,52.07
CC_UTS  (via drill 0.61)
  Top 0.254: v87.63,73.66 v87.63,109.22 | v173.35,93.98 170.81,91.44 170.81,81.92 E21.13 | v214.63,93.98 214.63,107.95 215.26,108.59 215.26,186.06 E09.1
  Bottom 0.254: E21.13 166.37,78.74 165.1,77.47 127,77.47 125.73,78.74 E29.13 121.92,78.74 118.11,74.93 115.57,74.93 113.03,72.39 88.9,72.39 v87.63,73.66 | v87.63,109.22 83.82,109.22 82.55,107.95 76.2,107.95 74.93,109.22 E38.5 | v173.35,93.98 v214.63,93.98 231.14,93.98 242.57,105.41 248.92,105.41 250.19,106.68 E03.9
CC_UTS\  (via drill 0.61)
  Top 0.254: v255.27,100.33 255.27,82.55 E02.11
  Bottom 0.254: v255.27,100.33 E03.8
CC_WRT_OK  (via drill 0.61)
  Top 0.254: v149.22,97.16 149.22,117.48 148.59,118.11 140.34,118.11 140.34,117.48 E26.2
  Bottom 0.254: v149.22,97.16 121.92,97.16 120.02,95.25 6.35,95.25 6.35,100.33 E46.6
CON_ALL_HALT  (via drill 0.61)
  Top 0.254: v13.97,140.34 13.97,120.65 E46.1
  Bottom 0.254: v13.97,140.34 24.77,151.13 26.04,151.13 27.3,152.4 J1.RR
DATA00  (via drill 0.61)
  Top 0.254: E05.12 222.88,34.93 222.88,15.88 220.98,13.97 EDGE$.AR1 | v194.31,107.95 194.94,107.32 194.94,46.36 195.58,45.72 v195.58,38.1
  Bottom 0.254: v194.31,107.95 190.5,107.95 189.23,109.22 E17.10 | v195.58,38.1 196.85,36.83 223.52,36.83 227.33,40.64 E05.12
DATA01  (via drill 0.61)
  Top 0.254: 217.81,36.83 222.25,36.83 E05.13 | 217.81,36.83 217.81,13.97 EDGE$.AS1 | v217.17,107.95 217.81,107.32 217.81,67.31 217.17,66.68 217.17,37.47 217.81,36.83
  Bottom 0.254: v217.17,107.95 208.28,107.95 207.01,109.22 E12.10
DATA02  (via drill 0.61)
  Top 0.254: v215.9,38.1 212.09,34.29 212.09,15.88 211.46,15.24 211.46,13.97 EDGE$.AU1 | v217.81,110.49 218.44,109.86 218.44,66.68 217.81,66.04 217.81,46.36 E05.4
  Bottom 0.254: v215.9,38.1 E05.4 | v217.81,110.49 226.06,110.49 227.33,109.22 E07.10
DATA03  (via drill 0.61)
  Top 0.254: EDGE$.AV1 208.28,13.97 208.91,14.61 208.91,36.83 v210.19,38.1 210.19,44.45 214.63,48.9 214.63,84.46 213.36,85.73 213.36,109.86 v210.19,113.03
  Bottom 0.254: v210.19,38.1 212.09,38.1 219.71,45.72 E05.3 | v210.19,113.03 190.5,113.03 189.23,114.3 E17.12
DATA04  (via drill 0.61)
  Top 0.254: E10.12 207.65,42.55 207.65,57.79 207.01,58.42 207.01,67.31 208.28,68.58 208.28,111.76 E12.12 | v153.03,16.51 153.03,15.88 151.13,13.97 EDGE$.BR1 | v188.59,18.42 201.93,31.75 v201.93,40.64
  Bottom 0.254: v153.03,16.51 154.94,18.42 v188.59,18.42 | E10.12 v201.93,40.64
DATA05  (via drill 0.61)
  Top 0.254: EDGE$.BS1 147.96,13.97 147.96,28.58 v149.86,30.48 145.41,34.93 145.41,39.37 148.59,39.37 149.22,40.01 149.22,45.09 153.67,45.09 157.48,48.9 157.48,53.34 156.84,53.98 156.84,99.06 v156.21,99.7 | v230.5,102.24 230.5,112.4 E07.12
  Bottom 0.254: v149.86,30.48 169.54,30.48 169.54,36.83 177.16,44.45 203.2,44.45 204.47,43.18 E10.13 | v230.5,102.24 227.97,99.7 163.19,99.7 162.56,99.06 156.84,99.06 v156.21,99.7
DATA06  (via drill 0.61)
  Top 0.254: v194.31,43.18 193.68,42.55 193.68,29.85 v184.15,20.32 | EDGE$.BU1 141.6,13.97 141.6,20.32 v142.24,20.96 135.89,27.31 v135.89,101.6
  Bottom 0.254: v184.15,20.32 183.51,20.96 v142.24,20.96 | v194.31,43.18 E10.4 | v135.89,101.6 171.45,101.6 179.07,109.22 E17.5
DATA07  (via drill 0.61)
  Top 0.254: 193.04,46.99 v194.31,45.72 | v193.04,109.22 193.04,46.99 | v140.34,15.88 138.43,13.97 EDGE$.BV1 | v182.25,19.69 193.04,30.48 193.04,46.99
  Bottom 0.254: v194.31,45.72 E10.3 | v193.04,109.22 E12.5 | v140.34,15.88 144.15,19.69 v182.25,19.69
DATA08  (via drill 0.61)
  Top 0.254: v216.53,110.49 216.53,108.59 215.26,107.32 215.26,104.14 215.9,103.51 215.9,48.9 214,46.99 214,44.45 v211.46,41.91 211.46,27.31 v210.19,26.04 | v20.95,21.59 20.95,17.15 17.78,13.97 EDGE$.DR1
  Bottom 0.254: v211.46,41.91 190.5,41.91 189.23,40.64 E15.12 | v216.53,110.49 217.81,111.76 E07.4 | v20.95,21.59 27.3,27.94 52.7,27.94 53.34,28.58 62.23,28.58 63.5,27.31 125.73,27.31 127,26.04 v210.19,26.04
DATA09  (via drill 0.61)
  Top 0.254: v184.15,104.14 184.15,64.14 184.78,63.5 184.78,43.82 v184.15,43.18 184.15,33.02 v175.9,24.77 | v19.68,19.05 14.61,13.97 EDGE$.DS1
  Bottom 0.254: v184.15,104.14 E17.7 | v184.15,43.18 E15.13 | v19.68,19.05 27.94,27.31 53.34,27.31 53.98,27.94 61.59,27.94 62.87,26.67 125.09,26.67 127,24.77 v175.9,24.77
DATA10  (via drill 0.61)
  Top 0.254: v177.16,102.24 v177.16,87.63 177.16,39.37 181.61,39.37 182.25,40.01 182.25,41.28 E15.4 | v15.88,87 15.88,21.59 8.26,13.97 EDGE$.DU1
  Bottom 0.254: v177.16,102.24 177.8,102.87 195.58,102.87 196.85,104.14 E12.7 | v15.88,87 17.14,88.27 55.88,88.27 57.78,86.36 97.79,86.36 99.06,87.63 114.3,87.63 115.57,88.9 146.69,88.9 147.96,87.63 v177.16,87.63
DATA11  (via drill 0.61)
  Top 0.254: v215.26,46.99 216.53,48.26 v216.53,104.14 | v9.53,63.5 9.53,18.42 5.08,13.97 EDGE$.DV1 | v183.51,63.5 184.15,62.87 184.15,49.53 E15.3
  Bottom 0.254: v215.26,46.99 182.88,46.99 181.61,45.72 E15.3 | v216.53,104.14 E07.7 | v9.53,63.5 11.43,65.41 36.83,65.41 38.1,64.14 119.38,64.14 120.65,65.41 123.83,65.41 125.73,63.5 v183.51,63.5
DF_COMP_WD  (via drill 0.61)
  Top 0.254: v165.1,114.3 E22.13 | E18.12 186.06,145.42 186.06,141.61 E18.9 | v176.53,118.11 178.44,120.02 178.44,140.34 E18.5
  Bottom 0.254: E22.3 v165.1,114.3 | E18.5 181.61,142.24 184.15,139.7 E18.9 | v176.53,118.11 170.18,118.11 168.91,116.84 E22.13
DF_DB00  (via drill 0.61)
  Top 0.254: 189.87,98.43 189.87,117.48 E17.14 | 189.87,98.43 189.87,83.19 E16.14 | 189.87,98.43 v188.59,98.43
  Bottom 0.254: E34.12 100.33,114.3 99.06,113.03 92.71,113.03 90.17,115.57 61.59,115.57 61.59,108.59 E42.9 64.77,106.68 68.58,102.87 120.65,102.87 123.19,100.33 153.67,100.33 155.57,98.43 v188.59,98.43
DF_DB01  (via drill 0.61)
  Top 0.254: v92.08,121.92 92.08,118.75 E34.2 | v185.42,122.56 185.42,144.78 E18.2 | E11.14 203.2,83.82 203.2,116.84 E12.14
  Bottom 0.254: v92.08,121.92 92.71,122.56 142.88,122.56 143.51,121.92 180.34,121.92 180.97,122.56 v185.42,122.56 190.5,122.56 192.41,120.65 203.2,120.65 204.47,119.38 E12.14
DF_DB02  (via drill 0.61)
  Top 0.254: E06.14 226.06,83.82 v226.06,97.16 226.06,116.84 E07.14 | v120.02,99.7 118.75,100.97 118.75,114.94 E30.2
  Bottom 0.254: E42.13 64.77,116.84 66.04,118.11 114.3,118.11 115.57,116.84 E30.2 | v226.06,97.16 155.57,97.16 153.03,99.7 v120.02,99.7
DF_DB03  (via drill 0.61)
  Top 0.254: v127,85.09 127,111.76 E30.12 | E17.13 186.06,114.94 186.06,85.73 E16.15
  Bottom 0.254: v127,85.09 176.53,85.09 179.07,82.55 185.42,82.55 186.69,83.82 E16.15
DF_HLD\  (via drill 0.61)
  Top 0.254: v59.05,35.56 59.05,45.09 E40.2 | v207.65,29.21 207.65,36.2 E10.11
  Bottom 0.254: v59.05,35.56 60.33,34.29 99.06,34.29 100.33,35.56 E32.8 102.87,35.56 109.22,29.21 v207.65,29.21
DF_SEL_ER  (via drill 0.61)
  Top 0.254: v76.83,48.26 76.83,67.95 E37.6
  Bottom 0.254: v76.83,48.26 78.11,46.99 98.42,46.99 99.69,45.72 E32.12
DF_SEL_ER\  (via drill 0.61)
  Top 0.254: E40.5 50.8,45.72 v50.8,52.07 R11.1
  Bottom 0.254: Q2.3 Q3.3 R11.1 | v50.8,52.07 96.52,52.07 100.33,48.26 E32.13
DF_TIME_ER  (via drill 0.61)
  Top 0.254: v98.42,139.7 99.06,140.34 v99.06,153.67 | v83.82,76.2 85.09,77.47 85.09,116.21 84.45,116.84 84.45,137.8 v86.36,139.7
  Bottom 0.254: E41.2 62.23,74.93 71.12,74.93 72.39,73.66 E37.5 74.93,73.66 76.2,74.93 82.55,74.93 v83.82,76.2 | v99.06,153.67 100.33,154.94 149.86,154.94 153.67,151.13 153.67,149.86 E27.13 | v98.42,139.7 E35.6 v86.36,139.7
DF_TIME_ER\  (via drill 0.61)
  Top 0.254: v77.47,142.24 77.47,138.43 71.12,132.08 71.12,100.97 57.78,87.63 57.78,52.71 E40.1 | v98.42,156.85 95.89,154.31 95.89,146.69 95.25,146.05 92.08,146.05 92.08,144.15 E35.5 | v137.79,156.85 E27.12
  Bottom 0.254: v77.47,142.24 78.74,143.51 91.44,143.51 92.71,142.24 E35.5 | v137.79,156.85 v98.42,156.85
F/R\  (via drill 0.61)
  Top 0.254: v78.74,144.78 78.74,139.7 E39.8
  Bottom 0.254: v78.74,144.78 77.47,146.05 67.31,146.05 64.77,148.59 29.84,148.59 28.57,149.86 J1.TT
GND  (via drill 0.61)
  Top 0.635: E13.12 200.03,150.5 200.03,170.82 E14.7 | E04.8 245.11,135.89 C3.2 | E08.9 E08.8 221.62,136.53 221.62,125.73 222.25,125.1 C7.2 222.25,120.65 E07.1 224.79,115.57 v224.79,90.81 224.79,72.39 E06.8 221.62,67.95 221.62,57.15 222.25,56.52 C5.2 | E08.1 C8.2 C9.2 | E04.1 245.11,156.21 C4.2 244.47,160.02 244.47,189.23 WTM.1 | v214,168.28 214,172.09 E09.7 | v212.72,15.24 212.72,13.97 EDGE$.AT1 | 248.28,66.04 248.28,66.68 E02.7 | 248.28,66.04 248.28,58.42 246.38,56.52 C1.2 246.38,55.25 245.75,54.61 245.75,37.47 E01.7 236.85,28.58 236.85,23.5 | 248.28,66.04 C2.2 | 236.85,23.5 236.85,21.59 C34.- 237.49,20.96 244.47,13.97 EDGE$.AF1 | 236.85,23.5 227.33,13.97 EDGE$.AN1 | E16.8 180.97,67.95 180.97,55.88 C13.2 | E11.8 199.39,67.31 C10.2 200.03,55.88 200.03,34.93 E10.8 | J1.VV J1.UU J1.SS J1.PP J1.MM J1.KK J1.HH J1.EE J1.CC J1.AA J1.Y J1.W J1.U J1.S J1.P J1.M J1.K J1.H J1.E J1.C J1.A J1.B | E12.1 199.39,120.65 C12.2 | E17.1 181.61,120.65 C14.2 181.61,135.89 E18.7 | C28.2 57.15,137.16 E43.7 | v87.63,135.89 C25.2 | C30.2 104.14,153.67 111.76,146.05 111.76,139.07 113.67,137.16 E31.7 | C17.2 172.72,114.94 170.81,116.84 170.81,121.29 165.1,127 165.1,132.08 E23.7 | v111.76,15.24 111.76,13.97 EDGE$.CF1 | EDGE$.CN1 93.34,13.97 v93.34,15.24 93.34,34.93 E32.7 90.17,39.37 90.17,40.64 E36.10 | C21.2 124.46,29.85 122.56,27.94 122.56,13.97 EDGE$.CC1 | EDGE$.BC1 184.15,13.97 184.15,15.24 v177.8,15.24 176.53,13.97 EDGE$.BF1 174.62,13.97 169.54,19.05 169.54,42.55 | 169.54,42.55 169.54,43.82 E20.12 | 169.54,42.55 E20.10 | E20.1 C16.2 E21.8 | E25.8 140.97,67.31 C18.2 141.6,55.88 141.6,49.53 | 141.6,49.53 148.59,49.53 149.22,50.17 149.22,69.85 152.4,73.03 C19.2
  Top 0.635: E29.8 C22.2 E28.1 118.75,48.9 118.75,42.55 E28.5 | 141.6,33.66 143.51,31.75 143.51,13.97 EDGE$.BT1 | 141.6,33.66 E24.7 | 141.6,49.53 141.6,33.66 | E44.1 13.97,52.07 C31.2 13.97,67.31 E45.8 | C44.1 C43.2 30.48,44.45 32.38,42.55 | 32.38,42.55 33.02,41.91 D2.A C42.1 C41.1 33.02,32.39 41.27,24.13 41.27,13.97 EDGE$.DF1 43.18,13.97 v44.45,15.24 50.8,15.24 50.8,13.97 EDGE$.DC1 52.7,13.97 55.24,16.51 55.24,20.32 | 32.38,42.55 24.13,34.29 24.13,13.97 EDGE$.DN1 | v10.79,15.24 10.79,13.97 EDGE$.DT1 | 55.24,20.32 55.24,34.93 E40.7 | 55.24,20.32 73.03,20.32 79.38,13.97 EDGE$.CT1 | E33.7 95.89,70.49 95.89,88.9 C23.2 95.25,102.87 E34.7 | E41.7 53.34,71.12 C26.2 53.98,86.36 56.52,88.9 C27.2 57.15,89.54 56.52,90.17 56.52,103.51 E42.7 C46.- 47.62,105.41 47.62,147.32 40.64,154.31 R37.2 | C24.2 E38.7 | Q4.3 33.02,121.29 36.83,117.48 36.83,109.86 38.1,108.59 R36.2
  Bottom 0.635: C20.2 150.5,165.1 158.12,172.72 E19.7 181.61,172.72 182.88,171.45 189.87,171.45 193.04,174.63 C15.2 193.68,175.26 196.22,172.72 E14.7 199.39,172.72 200.66,173.99 210.82,173.99 212.09,172.72 E09.7 | 232.41,137.16 E04.8 | E08.9 232.41,137.16 | C40.2 258.44,147.32 257.18,148.59 250.19,148.59 E04.1 | 232.41,161.93 242.57,161.93 244.47,160.02 C4.2 | 232.41,161.93 223.52,161.93 221.62,160.02 C8.2 | 232.41,137.16 232.41,161.93 | v214,168.28 214.63,167.64 C9.2 | v212.72,15.24 212.72,13.97 EDGE$.AT1 214.63,13.97 215.9,15.24 224.16,15.24 225.43,13.97 EDGE$.AN1 227.33,13.97 233.04,19.69 234.95,19.69 C34.- 237.49,19.69 238.76,19.69 243.21,15.24 | 243.21,15.24 244.47,13.97 EDGE$.AF2 | 243.21,15.24 252.73,15.24 254,13.97 EDGE$.AC2 | 220.34,92.71 201.29,92.71 200.03,91.44 C11.2 | 220.34,92.71 221.62,91.44 C6.2 | 224.79,92.71 220.34,92.71 | 224.79,92.71 231.14,92.71 242.57,104.14 E03.7 | 195.58,31.75 182.88,31.75 181.61,33.02 E15.8 | 195.58,31.75 196.85,33.02 E10.8 | 195.58,31.75 218.44,31.75 219.71,33.02 E05.8 | 195.58,69.85 182.88,69.85 181.61,68.58 E16.8 179.07,68.58 177.8,67.31 157.48,67.31 | 195.58,69.85 196.85,68.58 E11.8 | 195.58,69.85 218.44,69.85 219.71,68.58 E06.8 | v224.79,90.81 224.79,92.71 | C1.2 245.75,55.88 243.21,53.34 202.56,53.34 200.03,55.88 C10.2 | C12.2 198.75,124.46 197.49,125.73 183.51,125.73 182.25,124.46 C14.2 | E43.7 57.15,137.16 58.42,138.43 71.12,138.43 72.39,137.16 E39.7 74.93,137.16 76.2,135.89 v87.63,135.89 91.44,135.89 | 91.44,135.89 92.71,137.16 E35.7 | 114.3,135.89 115.57,137.16 E31.7 | 91.44,135.89 114.3,135.89 | 137.16,135.89 138.43,137.16 E27.7
  Bottom 0.635: 114.3,135.89 137.16,135.89 | 157.48,135.89 158.75,137.16 E23.7 | 137.16,135.89 157.48,135.89 | 157.48,135.89 168.91,135.89 170.18,137.16 E18.7 | C28.2 46.35,124.46 43.81,121.92 Q5.3 Q4.3 13.34,121.92 8.26,127 C48.1 7.62,128.91 25.4,146.69 J1.UU | EDGE$.CT1 81.28,13.97 82.55,15.24 90.81,15.24 92.08,13.97 EDGE$.CN1 | v111.76,15.24 113.03,13.97 EDGE$.CF2 | v111.76,15.24 110.49,16.51 108.58,16.51 105.41,19.69 C35.- 102.87,19.69 99.69,19.69 93.98,13.97 EDGE$.CN1 | v111.76,15.24 119.38,15.24 120.65,13.97 EDGE$.CC2 | EDGE$.BC2 184.15,13.97 182.88,15.24 v177.8,15.24 176.53,13.97 EDGE$.BF2 174.62,13.97 173.35,15.24 154.31,15.24 | 154.31,15.24 146.05,15.24 144.78,13.97 EDGE$.BT1 | 154.31,15.24 155.57,13.97 EDGE$.BN2 | E20.12 166.37,45.72 161.29,50.8 E20.1 | 120.02,37.47 123.19,40.64 E28.10 133.35,40.64 138.43,35.56 E24.7 | 120.02,37.47 119.38,36.83 | 119.38,36.83 118.11,35.56 E28.7 111.12,35.56 111.12,33.66 111.76,33.02 121.28,33.02 123.83,30.48 C21.2 | 120.02,37.47 E28.5 | 157.48,67.31 158.75,68.58 E21.8 | 157.48,67.31 142.24,67.31 140.97,68.58 E25.8 | 119.38,36.83 100.33,36.83 99.06,35.56 E32.7 | v93.34,15.24 93.34,13.97 EDGE$.CN1 | C47.2 8.26,60.96 13.34,55.88 C31.2 14.61,55.88 15.88,57.15 26.67,57.15 27.94,55.88 C43.2 | EDGE$.DC2 50.8,13.97 49.53,15.24 v44.45,15.24 43.18,13.97 EDGE$.DF2 41.27,13.97 40.01,15.24 20.95,15.24 | v10.79,15.24 10.79,13.97 EDGE$.DT1 11.43,13.97 12.7,15.24 20.95,15.24 | 20.95,15.24 22.23,13.97 EDGE$.DN1 | 114.3,105.41 115.57,104.14 E30.7 | 114.3,105.41 96.52,105.41 95.25,104.14 E34.7 | 114.3,105.41 137.16,105.41 138.43,104.14 E26.7 140.97,104.14 142.24,102.87 157.48,102.87 158.75,104.14 E22.7
  Bottom 0.635: E37.7 C33.2 67.94,68.58 66.67,67.31 | 66.67,67.31 58.42,67.31 57.15,68.58 E41.7 C44.1 | R37.2 41.27,154.94 43.81,157.48 C29.2 | C32.2 7.62,99.7 11.43,103.51 12.06,103.51 E46.7 13.97,104.14 16.51,101.6 34.92,101.6 37.47,104.14 R36.2 38.73,104.14 40.01,102.87 47.62,102.87 C46.- | C24.2 73.03,99.06 70.48,101.6 59.69,101.6 57.15,104.14 E42.7 | 91.44,67.31 92.71,68.58 E33.7 | 91.44,67.31 66.67,67.31 | 91.44,67.31 114.3,67.31 115.57,68.58 E29.8
  pour Bottom (isolate 0.254): 0,19.05 265.43,19.05 265.43,214.63 0,214.63
  pour Top (isolate 0.254): 0,19.05 265.43,19.05 265.43,214.63 0,214.63
INITIALIZE  (via drill 0.61)
  Top 0.254: v88.9,39.37 87.63,38.1 87.63,13.97 EDGE$.CR1
  Bottom 0.254: v88.9,39.37 111.76,39.37 115.57,43.18 E28.4
INTERNAL_IO
  Top 0.254: E33.4 92.08,74.3 92.08,57.79 98.42,51.44 98.42,13.97 EDGE$.CL1
IO_PAUSE
  Top 0.254: E28.9 119.38,33.02 119.38,13.97 EDGE$.CD1
IO_PAUSE\
  Top 0.254: E20.7 161.93,37.47 161.93,41.28 E20.4
  Bottom 0.254: E28.14 125.73,50.8 127,49.53 151.76,49.53 153.03,50.8 157.48,50.8 158.75,49.53 161.29,49.53 163.19,47.63 163.19,43.18 E20.4 158.75,43.18 156.21,40.64 E24.10
MD03  (via drill 0.61)
  Top 0.254: v151.13,23.5 151.13,34.29 E24.9 | v224.16,21.59 224.16,13.97 EDGE$.AP1
  Bottom 0.254: v151.13,23.5 153.03,21.59 v224.16,21.59
MD04  (via drill 0.61)
  Top 0.254: v161.93,44.45 163.83,42.55 163.83,15.24 165.1,13.97 EDGE$.BK1
  Bottom 0.254: v161.93,44.45 158.75,44.45 158.12,45.09 153.67,45.09 151.76,46.99 144.78,46.99 140.97,43.18 E24.4
MD05  (via drill 0.61)
  Top 0.254: v151.13,39.37 152.4,40.64 158.12,40.64 158.12,17.78 161.93,13.97 EDGE$.BL1
  Bottom 0.254: v151.13,39.37 142.24,39.37 140.97,40.64 E24.5
MD06  (via drill 0.61)
  Top 0.254: v155.57,35.56 157.48,33.66 157.48,15.24 158.75,13.97 EDGE$.BM1
  Bottom 0.254: v155.57,35.56 153.03,35.56 151.76,36.83 142.24,36.83 140.97,38.1 E24.6
MD07
  Top 0.254: W2W1.1 154.31,37.47 154.31,13.97 EDGE$.BP1
  Bottom 0.254: E20.5 161.93,38.74 161.93,36.83 156.21,36.83 W2W1.1
MD08  (via drill 0.61)
  Top 0.254: v34.29,29.21 33.66,28.58 33.66,13.97 EDGE$.DK1 | v152.4,27.31 W4W3.1
  Bottom 0.254: E20.6 158.75,38.1 156.84,40.01 154.31,40.01 W4W3.1 | v152.4,27.31 151.76,26.67 127.64,26.67 126.36,27.94 64.14,27.94 62.87,29.21 v34.29,29.21
MD09  (via drill 0.61)
  Top 0.254: v26.67,31.75 28.57,29.85 28.57,13.97 EDGE$.DL1
  Bottom 0.254: v26.67,31.75 17.78,31.75 13.97,35.56 E44.7
MD10  (via drill 0.61)
  Top 0.254: v25.4,33.02 25.4,13.97 EDGE$.DM1
  Bottom 0.254: v25.4,33.02 E44.9
MD11
  Top 0.254: E44.11 22.23,41.28 22.23,15.24 20.95,13.97 EDGE$.DP1
MTR0\  (via drill 0.61)
  Top 0.254: v120.65,64.14 120.65,67.31 E29.7 | v208.28,61.6 209.55,60.33 209.55,40.64 v208.28,39.37
  Bottom 0.254: v120.65,64.14 122.56,62.23 195.58,62.23 196.22,62.87 207.01,62.87 v208.28,61.6 | v208.28,39.37 200.66,39.37 199.39,40.64 E10.5
MTR1\  (via drill 0.61)
  Top 0.254: v114.94,62.87 114.94,74.3 E29.5 | v196.22,61.6 196.22,50.17 E10.2
  Bottom 0.254: v114.94,62.87 116.2,61.6 v196.22,61.6
MTR2\  (via drill 0.61)
  Top 0.254: v120.65,73.66 120.65,74.93 E29.4 | v173.35,39.37 171.45,41.28 171.45,69.85 E21.11
  Bottom 0.254: v120.65,73.66 121.92,72.39 165.1,72.39 166.37,73.66 E21.11 | v173.35,39.37 181.61,39.37 182.88,38.1 E15.11
MTR3\
  Top 0.254: E15.14 186.06,43.82 186.06,40.01 186.69,39.37 186.06,38.74 186.06,34.93 186.69,34.29 189.87,34.29 189.87,32.39 180.34,22.86 170.81,22.86 170.81,65.41 E21.9
MTR4\  (via drill 0.61)
  Top 0.254: v178.44,69.85 178.44,42.55 E15.5
  Bottom 0.254: v178.44,69.85 162.56,69.85 161.29,71.12 E21.7
MTR5\  (via drill 0.61)
  Top 0.254: v163.83,52.07 161.93,53.98 161.93,74.3 E21.5
  Bottom 0.254: v163.83,52.07 175.26,52.07 179.07,48.26 E15.2
N$1  (via drill 0.61)
  Top 0.254: v212.09,85.09 212.09,75.57 213.36,74.3 R3.1
  Bottom 0.254: 195.58,87.63 182.88,87.63 181.61,86.36 E16.1 | 195.58,87.63 196.85,86.36 E11.1 | 212.09,87.63 195.58,87.63 | 212.09,87.63 218.44,87.63 219.71,86.36 E06.1 | E16.10 189.23,71.12 189.87,71.76 196.22,71.76 196.85,72.39 203.2,72.39 204.47,71.12 E11.10 207.01,71.12 209.55,73.66 R3.1 214,73.66 215.26,72.39 226.06,72.39 227.33,71.12 E06.10 | v212.09,85.09 212.09,87.63
N$2  (via drill 0.61)
  Top 0.254: v120.02,132.72 120.02,135.26 E31.9 | v233.04,133.35 241.3,125.1 241.3,88.9 E02.1
  Bottom 0.254: v120.02,132.72 120.65,132.08 231.78,132.08 v233.04,133.35
N$3
  Top 0.254: E16.2 182.25,85.73 182.25,112.4 E17.3
N$4
  Top 0.254: E16.3 178.44,83.19 178.44,114.94 E17.2
N$5  (via drill 0.61)
  Top 0.254: E21.14 167,81.92 167,83.19 E21.15 | v163.83,71.12 162.56,72.39 162.56,76.2 161.29,77.47 158.12,77.47 158.12,79.38 E21.3 159.38,81.92 159.38,83.19 E21.2 159.38,84.46 159.38,85.73 E21.1 | E29.3 116.2,81.92 116.2,83.19 E29.2 116.2,84.46 116.2,85.73 E29.1 | E29.10 126.36,73.03 126.36,79.38 E29.14 123.83,81.92 123.83,83.19 E29.15
  Bottom 0.254: v163.83,71.12 E21.10 | E21.14 E21.3 158.75,81.28 157.48,82.55 133.99,82.55 132.72,81.28 R2.1 E29.14 E29.3
N$6
  Top 0.254: E43.9 61.59,141.61 61.59,147.96 E43.13 65.41,151.77 65.41,153.04 64.77,153.67 R14.2
N$7  (via drill 0.61)
  Top 0.254: v155.57,76.2 155.57,83.82 147.96,91.44 147.96,103.51 E26.8
  Bottom 0.254: E06.6 219.71,73.66 218.44,74.93 200.66,74.93 199.39,73.66 E11.6 196.85,73.66 195.58,72.39 182.88,72.39 181.61,73.66 E16.6 176.53,73.66 175.26,74.93 156.84,74.93 v155.57,76.2
N$8
  Top 0.254: E11.2 200.66,86.36 200.66,111.76 E12.3
N$9
  Top 0.254: E11.3 196.22,83.19 196.22,114.94 E12.2
N$11
  Top 0.254: E11.15 207.65,85.73 207.65,99.7 203.84,103.51 203.84,114.94 E12.13
N$13
  Top 0.254: E06.2 223.52,86.36 223.52,111.76 E07.3
N$14
  Top 0.254: E06.3 219.07,83.19 219.07,114.94 E07.2
N$16
  Top 0.254: E06.15 230.5,85.73 230.5,99.7 226.69,103.51 226.69,114.94 E07.13
N$17
  Top 0.254: E14.13 203.84,183.52 203.84,179.71 E14.10 | 219.07,179.71 219.07,183.52 E09.13 | E09.10 219.07,179.71 | 219.07,179.71 219.07,151.77 E08.3 | E14.1 196.22,186.06 196.22,182.25 E14.4
  Bottom 0.254: R22.2 177.8,187.96 179.07,189.23 195.58,189.23 196.85,187.96 E14.1 | E08.3 222.25,149.86 223.52,148.59 229.87,148.59 230.5,147.96 230.5,142.88 229.24,142.88 E08.11 | E14.4 199.39,180.34 201.93,177.8 E14.10 207.01,177.8 209.55,180.34 E09.4 217.17,180.34 219.71,177.8 E09.10
N$18  (via drill 0.61)
  Top 0.254: v107.95,74.93 107.31,75.57 107.31,111.13 115.57,119.38 E30.1
  Bottom 0.254: v107.95,74.93 83.82,74.93 82.55,73.66 E37.10
N$20  (via drill 0.61)
  Top 0.254: E43.10 62.87,142.88 62.87,144.15 E43.11 66.04,147.32 66.04,163.2 65.41,163.83 65.41,173.99 68.58,177.17 R13.2 | v135.89,116.84 134.62,118.11 v134.62,160.02
  Bottom 0.254: v135.89,116.84 138.43,114.3 E26.3 | v134.62,160.02 118.11,176.53 70.48,176.53 69.22,177.8 R13.2
N$22  (via drill 0.61)
  Top 0.254: E37.2 75.56,83.19 75.56,117.48 E38.1 74.3,120.02 74.3,133.99 v78.74,138.43
  Bottom 0.254: v78.74,138.43 137.16,138.43 138.43,139.7 E27.6
N$25  (via drill 0.61)
  Top 0.254: v66.04,46.99 65.41,47.63 65.41,66.68 E41.8
  Bottom 0.254: v66.04,46.99 74.93,46.99 75.56,46.36 79.38,46.36 80.01,45.72 E36.12
N$29
  Bottom 0.254: E26.9 148.59,106.68 149.86,105.41 165.1,105.41 166.37,104.14 E22.8
N$30  (via drill 0.61)
  Top 0.254: v121.28,109.86 121.28,133.99 E31.8
  Bottom 0.254: v121.28,109.86 123.19,107.95 163.83,107.95 166.37,105.41 168.91,105.41 169.54,106.05 169.54,108.59 168.28,108.59 E22.10
N$31
  Top 0.254: E22.6 157.48,104.14 157.48,76.2 E21.6
  Bottom 0.254: E29.6 118.11,73.66 119.38,74.93 155.57,74.93 156.84,73.66 E21.6
N$32
  Bottom 0.254: E18.13 189.23,149.86 194.31,154.94 E13.1
N$33  (via drill 0.61)
  Top 0.254: v185.42,147.32 182.25,150.5 v182.25,154.94 | E39.1 74.3,153.04 74.3,154.94 v74.93,155.58 R8.1
  Bottom 0.254: v182.25,154.94 181.61,155.58 v74.93,155.58 | v185.42,147.32 E18.11
N$34
  Bottom 0.254: E18.8 E13.8
N$35
  Bottom 0.254: E31.12 125.73,147.32 127,148.59 195.58,148.59 196.85,147.32 E13.4 E13.13
N$36  (via drill 0.61)
  Top 0.254: v76.83,133.35 76.83,81.92 E37.3
  Bottom 0.254: v76.83,133.35 78.11,134.62 172.72,134.62 173.99,135.89 181.61,135.89 | 181.61,135.89 182.25,136.53 182.25,139.07 180.97,139.07 E18.6 | 181.61,135.89 199.39,135.89 E13.11
N$37  (via drill 0.61)
  Top 0.254: v162.56,113.03 162.56,116.84 E22.1
  Bottom 0.254: v162.56,113.03 163.83,111.76 E22.11
N$38  (via drill 0.61)
  Top 0.254: v77.47,149.86 78.74,151.13 78.74,159.39 | R9.1 78.74,159.39 | v191.13,153.04 v191.13,142.24 | 78.74,159.39 v78.11,159.39
  Bottom 0.254: v77.47,149.86 74.93,147.32 E39.3 | v191.13,153.04 186.06,158.12 85.09,158.12 83.82,159.39 v78.11,159.39 | v191.13,142.24 E18.10
N$39  (via drill 0.61)
  Top 0.254: 100.33,185.42 92.71,185.42 87.63,180.34 87.63,178.44 83.82,174.63 83.82,152.4 E39.13 | 100.33,185.42 R10.1 | v114.3,149.86 105.41,158.75 105.41,188.6 104.78,189.23 101.6,189.23 101.6,186.69 100.33,185.42
  Bottom 0.254: v114.3,149.86 115.57,148.59 118.11,148.59 120.65,146.05 177.8,146.05 179.07,144.78 E18.4
N$40  (via drill 0.61)
  Top 0.254: v78.11,77.47 78.11,43.18 E36.11
  Bottom 0.254: v78.11,77.47 66.04,77.47 64.77,78.74 E41.12
N$41  (via drill 0.61)
  Top 0.254: v119.38,77.47 121.92,74.93 121.92,57.79 123.19,56.52 v123.19,53.34 | v208.28,58.42 208.28,40.64 207.01,39.37 203.84,39.37 203.84,43.82 E10.14
  Bottom 0.254: v119.38,77.47 80.01,77.47 78.74,76.2 E37.4 | v123.19,53.34 145.41,53.34 149.86,57.79 207.65,57.79 v208.28,58.42
N$42
  Top 0.254: E36.3 73.03,46.36 73.03,47.63 E36.2 71.75,50.17 71.75,104.78 E38.6
N$43
  Top 0.254: E38.4 73.03,112.4 73.03,113.67 E38.3
N$44  (via drill 0.61)
  Top 0.254: v60.33,39.37 59.69,40.01 v59.69,74.93
  Bottom 0.254: v60.33,39.37 82.55,39.37 83.82,38.1 E32.6 | v59.69,74.93 E41.3
N$45  (via drill 0.61)
  Top 0.254: v58.42,50.8 58.42,82.55 64.77,82.55 65.41,81.92 65.41,78.11 E41.11
  Bottom 0.254: v58.42,50.8 59.69,49.53 91.44,49.53 92.71,48.26 E32.2
N$46  (via drill 0.61)
  Top 0.254: v70.48,71.12 71.12,70.49 71.12,43.18 72.39,41.91 91.44,41.91 91.44,40.64 92.71,39.37 95.89,39.37 95.89,41.28 E32.4
  Bottom 0.254: v70.48,71.12 E41.9
N$47  (via drill 0.61)
  Top 0.254: v74.3,96.52 74.3,84.46 E37.1 | v121.28,100.97 122.56,102.24 122.56,132.72 126.36,136.53 126.36,142.88 E31.11
  Bottom 0.254: v74.3,96.52 110.49,96.52 114.94,100.97 v121.28,100.97
N$48  (via drill 0.61)
  Top 0.254: E35.11 99.69,146.69 99.69,147.96 E35.13 | v120.02,145.42 123.19,142.24 E31.10
  Bottom 0.254: v120.02,145.42 119.38,146.05 104.14,146.05 102.87,144.78 E35.11
N$49
  Bottom 0.254: E35.3 E35.12
N$50
  Top 0.254: E35.4 97.16,141.61 97.16,139.7 99.69,137.16 E35.8
N$51
  Top 0.254: D1.C R48.2 43.18,57.15 46.35,57.15 46.99,56.52 46.99,37.47 45.72,36.2 Q1.2
N$52
  Top 0.254: Q1.1 45.72,33.66 44.45,34.93 44.45,48.26 45.72,49.53 D5.C R41.2
N$53
  Top 0.254: Q1.3 43.18,36.2 41.91,37.47 41.91,46.99 39.37,49.53 39.37,64.14 38.1,65.41 R27.1
  Bottom 0.254: E32.9 100.33,38.1 99.06,36.83 45.09,36.83 43.81,35.56 Q1.3
N$54
  Top 0.254: D3.A 35.56,41.91 33.02,44.45 D2.C
N$55
  Top 0.254: D10.C R40.2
